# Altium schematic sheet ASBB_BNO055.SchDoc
size A4
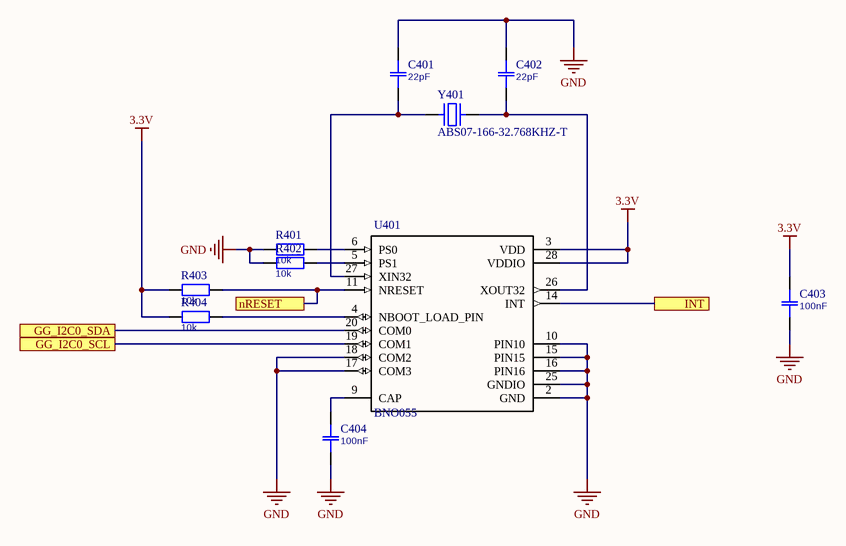
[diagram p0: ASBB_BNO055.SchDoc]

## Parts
C401  22pF  [0603]
C402  22pF  [0603]
C403  100nF  [0603]
C404  100nF  [0603]
R401  10k  [0603]
R402  10k  [0603]
R403  10k  [0603]
R404  10k  [0603]
U401  BNO055  [LGA28R50P4X10_380X520X100]
Y401  ABS07-166-32.768KHZ-T  [ABRACON ABS07]

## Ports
GG_I2C0_SCL, GG_I2C0_SDA, INT, nRESET

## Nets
3.3V: C403.2 R403.1 R404.1 U401.3(VDD) U401.28(VDDIO)
GND: C401.2 C402.2 C403.1 C404.1 R401.1 R402.1 U401.2(GND) U401.10(PIN10) U401.15(PIN15) U401.16(PIN16) U401.17(COM3) U401.18(COM2) U401.25(GNDIO)
GG_I2C0_SCL: U401.19(COM1) ; port GG_I2C0_SCL
GG_I2C0_SDA: U401.20(COM0) ; port GG_I2C0_SDA
INT: U401.14(INT) ; port INT
nRESET: R403.2 U401.11(NRESET) ; port nRESET
NetC401_1: C401.1 U401.27(XIN32) Y401.1
NetC402_1: C402.1 U401.26(XOUT32) Y401.2
NetC404_2: C404.2 U401.9(CAP)
NetR401_2: R401.2 U401.6(PS0)
NetR402_2: R402.2 U401.5(PS1)
NetR404_2: R404.2 U401.4(NBOOT_LOAD_PIN)

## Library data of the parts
C401-C404 = Capacitor
R401-R404 = Resistor
U401 = BNO055: BNO055 9-axis Absolute Orientation Sensor _ SiP _ w/Sensors and Sensor Fusion; MF: Bosch
Y401 = Abracon Crystal ABS06: SMT Crystal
